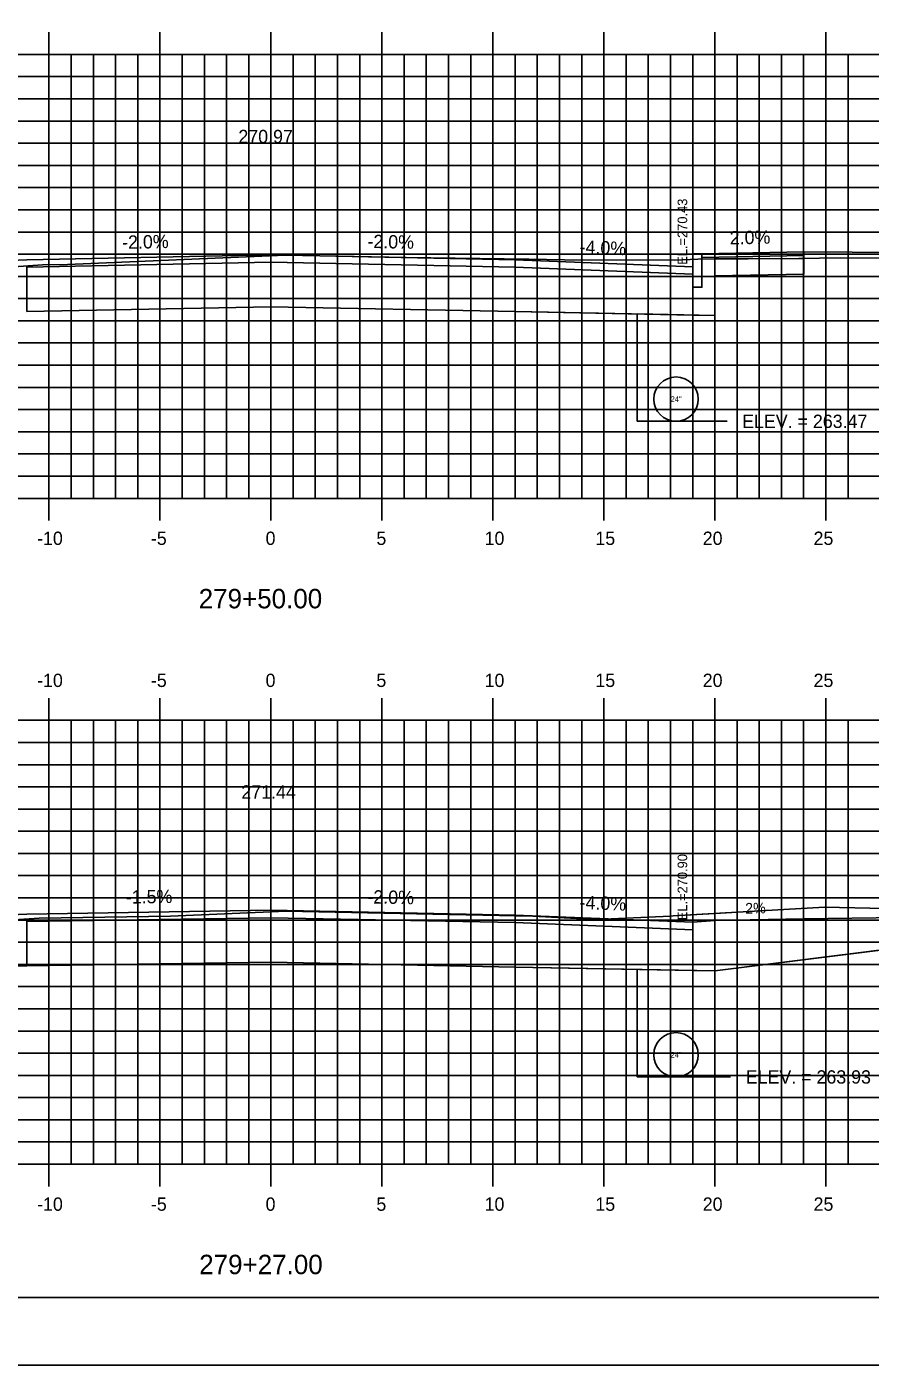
# Model space of a CAD drawing. Extents: x 854899 to 855069, y 366268 to 366378.
# Drawn here: x 854970.8 to 855008.8, y 366268.2 to 366328.5 of the extents above; entities that cross this region are included whole.
import ezdxf

# ---------------------------------------------------------------- set-up
doc = ezdxf.new("R2010")
doc.units = 0
for name, color, linetype in [('ANNOTATION', 7, 'Continuous'), ('BORDER', 7, 'Continuous'), ('D_Curb_Type_1_Rt', 7, 'Continuous'), ('D_Roadway_Centerline', 7, 'Continuous'), ('D_Roadway_Centerline_Text', 7, 'Continuous'), ('D_Roadway_Drive_Gravel_RT', 7, 'Continuous'), ('D_Roadway_Drive_SubGrade', 7, 'Continuous'), ('D_Roadway_Edge_Shoulder', 7, 'Continuous'), ('D_Roadway_FinishedGrade', 7, 'Continuous'), ('D_Roadway_Sidewalks_Paved', 7, 'Continuous'), ('D_Roadway_SubGrade', 7, 'Continuous'), ('D_Text_Standard', 7, 'Continuous'), ('H_V ANNOTATION', 7, 'Continuous'), ('JUNK COM EXC', 7, 'Continuous'), ('junk strct exc', 7, 'Continuous'), ('MAJOR', 7, 'Continuous'), ('MINOR', 7, 'Continuous'), ('PDRAIN', 7, 'Continuous'), ('PLOT BOUNDARY', 7, 'Continuous'), ('S_Roadway_Centerline', 7, 'Continuous')]:
    doc.layers.add(name, color=color, linetype=linetype)

msp = doc.modelspace()

# ---------------------------------------------------------------- linework, layer by layer
at = {"layer": 'BORDER'}
msp.add_line((854906.774, 366271.236), (855066.774, 366271.236), dxfattribs=at)
at = {"layer": 'D_Curb_Type_1_Rt'}
msp.add_lwpolyline([(855001.193, 366318.249), (855001.193, 366316.749), (855000.777, 366316.749), (855000.777, 366318.249)], close=True, dxfattribs=at)
at = {"layer": 'D_Roadway_Centerline'}
msp.add_lwpolyline([(854970.774, 366317.986), (854981.774, 366318.206), (854992.774, 366317.986)], dxfattribs=at)
at = {"layer": 'D_Roadway_Drive_Gravel_RT'}
for p, q in [((855001.774, 366288.213), (855005.774, 366288.293)), ((855005.774, 366288.293), (855032.774, 366288.63)), ((855000.774, 366288.133), (855001.774, 366288.213))]:
    msp.add_line(p, q, dxfattribs=at)
at = {"layer": 'D_Roadway_Drive_SubGrade'}
for p, q in [((855000.775, 366315.492), (855001.775, 366315.472)), ((855001.774, 366285.94), (855011.774, 366287.201)), ((855000.774, 366285.96), (855001.774, 366285.94))]:
    msp.add_line(p, q, dxfattribs=at)
at = {"layer": 'D_Roadway_Edge_Shoulder'}
msp.add_line((855000.774, 366317.665), (855000.774, 366317.333), dxfattribs=at)
for points in [[(854962.774, 366317.666), (854970.774, 366317.986), (854981.774, 366318.206), (854992.774, 366317.986), (855000.774, 366317.665)], [(854962.774, 366288.184), (854970.774, 366288.504), (854981.774, 366288.674), (854992.774, 366288.453), (855000.774, 366288.133)]]:
    msp.add_lwpolyline(points, dxfattribs=at)
at = {"layer": 'D_Roadway_FinishedGrade'}
msp.add_line((855005.782, 366318.34), (855023.706, 366318.244), dxfattribs=at)
at = {"layer": 'D_Roadway_Sidewalks_Paved'}
msp.add_lwpolyline([(855001.194, 366318.248), (855005.782, 366318.34), (855005.782, 366318.173), (855001.194, 366318.081)], close=True, dxfattribs=at)
at = {"layer": 'D_Roadway_SubGrade'}
for points in [[(854970.774, 366315.652), (854970.774, 366317.652), (854981.774, 366317.872), (854992.774, 366317.652), (854992.774, 366315.652), (854981.774, 366315.872)], [(854992.774, 366317.652), (855000.774, 366317.333), (855000.774, 366315.493), (854992.774, 366315.652)], [(854970.774, 366286.171), (854970.774, 366288.171), (854981.774, 366288.34), (854992.774, 366288.12), (854992.774, 366286.12), (854981.774, 366286.34)], [(854992.774, 366288.12), (855000.774, 366287.8), (855000.774, 366285.96), (854992.774, 366286.12)]]:
    msp.add_lwpolyline(points, close=True, dxfattribs=at)
msp.add_lwpolyline([(855005.782, 366318.173), (855005.782, 366317.34), (855001.777, 366317.26), (855001.777, 366315.472), (855000.777, 366315.492)], dxfattribs=at)
at = {"layer": 'D_Text_Standard'}
for points in [[(855001.775, 366310.706), (855001.642, 366310.706), (855002.322, 366310.706)], [(855001.774, 366281.166), (855001.804, 366281.166), (855002.484, 366281.166)]]:
    msp.add_lwpolyline(points, dxfattribs=at)
at = {"layer": 'JUNK COM EXC'}
for points in [[(854970.774, 366315.652), (854981.774, 366315.872), (854992.774, 366315.652), (855001.775, 366315.472), (855001.777, 366317.26), (855005.782, 366317.34), (855005.782, 366318.046), (855003.277, 366318.029), (855001.774, 366318.021), (855001.001, 366318.016), (854999.964, 366317.964), (854995.003, 366317.976), (854993.388, 366318.007), (854987.873, 366318.081), (854982.41, 366318.199), (854972.612, 366317.778), (854971.488, 366317.76), (854970.188, 366317.674)], [(855001.774, 366288.529), (854999.893, 366288.419), (854999.77, 366288.409), (854996.433, 366288.257), (854996.105, 366288.282), (854993.573, 366288.403), (854989.068, 366288.497), (854982.457, 366288.64), (854977.246, 366288.416), (854971.338, 366288.32), (854966.506, 366288), (854965.316, 366287.948), (854963.414, 366288.013), (854961.774, 366288.084), (854961.774, 366285.991), (854970.774, 366286.171), (854981.774, 366286.34), (854992.774, 366286.12), (855001.778, 366285.94), (855001.778, 366287.562)]]:
    msp.add_lwpolyline(points, dxfattribs=at)
msp.add_lwpolyline([(855001.774, 366285.94), (855011.774, 366287.201), (855032.774, 366287.463), (855032.774, 366288.63), (855029.947, 366288.626), (855028.392, 366288.676), (855026.837, 366288.727), (855022.702, 366288.715), (855018.567, 366288.702), (855014.002, 366288.726), (855009.438, 366288.75), (855008.079, 366288.784), (855006.72, 366288.819), (855003.306, 366288.619), (855001.774, 366288.529)], close=True, dxfattribs=at)
at = {"layer": 'junk strct exc'}
msp.add_lwpolyline([(854998.275, 366315.542), (854998.275, 366310.706), (855001.775, 366310.706), (855001.775, 366315.472)], close=True, dxfattribs=at)
at = {"layer": 'MAJOR'}
for p, q in [((854971.774, 366328.238), (854971.774, 366327.236)), ((854976.774, 366328.238), (854976.774, 366327.236)), ((854981.774, 366328.238), (854981.774, 366327.236)), ((854986.774, 366328.238), (854986.774, 366327.236)), ((854991.774, 366328.238), (854991.774, 366327.236)), ((854996.774, 366328.238), (854996.774, 366327.236)), ((855001.774, 366328.238), (855001.774, 366327.236)), ((855006.774, 366328.238), (855006.774, 366327.236)), ((854911.774, 366327.236), (855051.774, 366327.236)), ((854911.774, 366327.236), (855051.774, 366327.236)), ((854971.774, 366307.236), (854971.774, 366327.236)), ((854976.774, 366307.236), (854976.774, 366327.236)), ((854981.774, 366307.236), (854981.774, 366327.236)), ((854986.774, 366307.236), (854986.774, 366327.236)), ((854991.774, 366307.236), (854991.774, 366327.236)), ((854996.774, 366307.236), (854996.774, 366327.236)), ((855001.774, 366307.236), (855001.774, 366327.236)), ((855006.774, 366307.236), (855006.774, 366327.236)), ((854911.774, 366322.236), (855051.774, 366322.236)), ((854911.774, 366317.236), (855051.774, 366317.236)), ((854911.774, 366312.236), (855051.774, 366312.236)), ((854911.774, 366307.236), (855051.774, 366307.236)), ((854911.774, 366307.236), (855051.774, 366307.236)), ((854971.774, 366306.234), (854971.774, 366307.236)), ((854976.774, 366306.234), (854976.774, 366307.236)), ((854981.774, 366306.234), (854981.774, 366307.236)), ((854986.774, 366306.234), (854986.774, 366307.236)), ((854991.774, 366306.234), (854991.774, 366307.236)), ((854996.774, 366306.234), (854996.774, 366307.236)), ((855001.774, 366306.234), (855001.774, 366307.236)), ((855006.774, 366306.234), (855006.774, 366307.236)), ((854971.774, 366298.238), (854971.774, 366297.236)), ((854976.774, 366298.238), (854976.774, 366297.236)), ((854981.774, 366298.238), (854981.774, 366297.236)), ((854986.774, 366298.238), (854986.774, 366297.236)), ((854991.774, 366298.238), (854991.774, 366297.236)), ((854996.774, 366298.238), (854996.774, 366297.236)), ((855001.774, 366298.238), (855001.774, 366297.236)), ((855006.774, 366298.238), (855006.774, 366297.236)), ((854911.774, 366297.236), (855051.774, 366297.236)), ((854911.774, 366297.236), (855051.774, 366297.236)), ((854971.774, 366277.236), (854971.774, 366297.236)), ((854976.774, 366277.236), (854976.774, 366297.236)), ((854981.774, 366277.236), (854981.774, 366297.236)), ((854986.774, 366277.236), (854986.774, 366297.236)), ((854991.774, 366277.236), (854991.774, 366297.236)), ((854996.774, 366277.236), (854996.774, 366297.236)), ((855001.774, 366277.236), (855001.774, 366297.236)), ((855006.774, 366277.236), (855006.774, 366297.236)), ((854911.774, 366292.236), (855051.774, 366292.236)), ((854911.774, 366287.236), (855051.774, 366287.236)), ((854911.774, 366282.236), (855051.774, 366282.236)), ((854911.774, 366277.236), (855051.774, 366277.236)), ((854911.774, 366277.236), (855051.774, 366277.236)), ((854971.774, 366276.234), (854971.774, 366277.236)), ((854976.774, 366276.234), (854976.774, 366277.236)), ((854981.774, 366276.234), (854981.774, 366277.236)), ((854986.774, 366276.234), (854986.774, 366277.236)), ((854991.774, 366276.234), (854991.774, 366277.236)), ((854996.774, 366276.234), (854996.774, 366277.236)), ((855001.774, 366276.234), (855001.774, 366277.236)), ((855006.774, 366276.234), (855006.774, 366277.236))]:
    msp.add_line(p, q, dxfattribs=at)
at = {"layer": 'MINOR'}
for p, q in [((854972.774, 366307.236), (854972.774, 366327.236)), ((854973.774, 366307.236), (854973.774, 366327.236)), ((854974.774, 366307.236), (854974.774, 366327.236)), ((854975.774, 366307.236), (854975.774, 366327.236)), ((854977.774, 366307.236), (854977.774, 366327.236)), ((854978.774, 366307.236), (854978.774, 366327.236)), ((854979.774, 366307.236), (854979.774, 366327.236)), ((854980.774, 366307.236), (854980.774, 366327.236)), ((854982.774, 366307.236), (854982.774, 366327.236)), ((854983.774, 366307.236), (854983.774, 366327.236)), ((854984.774, 366307.236), (854984.774, 366327.236)), ((854985.774, 366307.236), (854985.774, 366327.236)), ((854987.774, 366307.236), (854987.774, 366327.236)), ((854988.774, 366307.236), (854988.774, 366327.236)), ((854989.774, 366307.236), (854989.774, 366327.236)), ((854990.774, 366307.236), (854990.774, 366327.236)), ((854992.774, 366307.236), (854992.774, 366327.236)), ((854993.774, 366307.236), (854993.774, 366327.236)), ((854994.774, 366307.236), (854994.774, 366327.236)), ((854995.774, 366307.236), (854995.774, 366327.236)), ((854997.774, 366307.236), (854997.774, 366327.236)), ((854998.774, 366307.236), (854998.774, 366327.236)), ((854999.774, 366307.236), (854999.774, 366327.236)), ((855000.774, 366307.236), (855000.774, 366327.236)), ((855002.774, 366307.236), (855002.774, 366327.236)), ((855003.774, 366307.236), (855003.774, 366327.236)), ((855004.774, 366307.236), (855004.774, 366327.236)), ((855005.774, 366307.236), (855005.774, 366327.236)), ((855007.774, 366307.236), (855007.774, 366327.236)), ((854911.774, 366326.236), (855051.774, 366326.236)), ((854911.774, 366325.236), (855051.774, 366325.236)), ((854911.774, 366324.236), (855051.774, 366324.236)), ((854911.774, 366323.236), (855051.774, 366323.236)), ((854911.774, 366321.236), (855051.774, 366321.236)), ((854911.774, 366320.236), (855051.774, 366320.236)), ((854911.774, 366319.236), (855051.774, 366319.236)), ((854911.774, 366318.236), (855051.774, 366318.236)), ((854911.774, 366316.236), (855051.774, 366316.236)), ((854911.774, 366315.236), (855051.774, 366315.236)), ((854911.774, 366314.236), (855051.774, 366314.236)), ((854911.774, 366313.236), (855051.774, 366313.236)), ((854911.774, 366311.236), (855051.774, 366311.236)), ((854911.774, 366310.236), (855051.774, 366310.236)), ((854911.774, 366309.236), (855051.774, 366309.236)), ((854911.774, 366308.236), (855051.774, 366308.236)), ((854972.774, 366277.236), (854972.774, 366297.236)), ((854973.774, 366277.236), (854973.774, 366297.236)), ((854974.774, 366277.236), (854974.774, 366297.236)), ((854975.774, 366277.236), (854975.774, 366297.236)), ((854977.774, 366277.236), (854977.774, 366297.236)), ((854978.774, 366277.236), (854978.774, 366297.236)), ((854979.774, 366277.236), (854979.774, 366297.236)), ((854980.774, 366277.236), (854980.774, 366297.236)), ((854982.774, 366277.236), (854982.774, 366297.236)), ((854983.774, 366277.236), (854983.774, 366297.236)), ((854984.774, 366277.236), (854984.774, 366297.236)), ((854985.774, 366277.236), (854985.774, 366297.236)), ((854987.774, 366277.236), (854987.774, 366297.236)), ((854988.774, 366277.236), (854988.774, 366297.236)), ((854989.774, 366277.236), (854989.774, 366297.236)), ((854990.774, 366277.236), (854990.774, 366297.236)), ((854992.774, 366277.236), (854992.774, 366297.236)), ((854993.774, 366277.236), (854993.774, 366297.236)), ((854994.774, 366277.236), (854994.774, 366297.236)), ((854995.774, 366277.236), (854995.774, 366297.236)), ((854997.774, 366277.236), (854997.774, 366297.236)), ((854998.774, 366277.236), (854998.774, 366297.236)), ((854999.774, 366277.236), (854999.774, 366297.236)), ((855000.774, 366277.236), (855000.774, 366297.236)), ((855002.774, 366277.236), (855002.774, 366297.236)), ((855003.774, 366277.236), (855003.774, 366297.236)), ((855004.774, 366277.236), (855004.774, 366297.236)), ((855005.774, 366277.236), (855005.774, 366297.236)), ((855007.774, 366277.236), (855007.774, 366297.236)), ((854911.774, 366296.236), (855051.774, 366296.236)), ((854911.774, 366295.236), (855051.774, 366295.236)), ((854911.774, 366294.236), (855051.774, 366294.236)), ((854911.774, 366293.236), (855051.774, 366293.236)), ((854911.774, 366291.236), (855051.774, 366291.236)), ((854911.774, 366290.236), (855051.774, 366290.236)), ((854911.774, 366289.236), (855051.774, 366289.236)), ((854911.774, 366288.236), (855051.774, 366288.236)), ((854911.774, 366286.236), (855051.774, 366286.236)), ((854911.774, 366285.236), (855051.774, 366285.236)), ((854911.774, 366284.236), (855051.774, 366284.236)), ((854911.774, 366283.236), (855051.774, 366283.236)), ((854911.774, 366281.236), (855051.774, 366281.236)), ((854911.774, 366280.236), (855051.774, 366280.236)), ((854911.774, 366279.236), (855051.774, 366279.236)), ((854911.774, 366278.236), (855051.774, 366278.236))]:
    msp.add_line(p, q, dxfattribs=at)
at = {"layer": 'PDRAIN'}
for points in [[(854998.275, 366315.542), (854998.275, 366310.706), (855001.775, 366310.706), (855001.775, 366315.472)], [(854998.274, 366286.002), (854998.274, 366281.166), (855001.774, 366281.166), (855001.774, 366285.932)]]:
    msp.add_lwpolyline(points, dxfattribs=at)
for centre in [(855000.025, 366311.706), (855000.024, 366282.166)]:
    msp.add_circle(centre, 1, dxfattribs=at)
at = {"layer": 'PLOT BOUNDARY'}
msp.add_lwpolyline([(854898.681, 366268.177), (855068.681, 366268.177), (855068.681, 366378.177), (854898.681, 366378.177)], close=True, dxfattribs=at)
at = {"layer": 'S_Roadway_Centerline'}
for points in [[(854924.068, 366316.94), (854929.097, 366317.144), (854935.552, 366317.258), (854949.789, 366317.41), (854960.814, 366317.707), (854961.589, 366317.66), (854964.403, 366317.388), (854965.385, 366317.346), (854970.188, 366317.674), (854971.488, 366317.76), (854972.612, 366317.778), (854982.41, 366318.199), (854987.873, 366318.081), (854993.388, 366318.007), (854995.003, 366317.976), (854999.964, 366317.964), (855001.001, 366318.016), (855005.553, 366318.042), (855007.414, 366318.074), (855018.059, 366317.982)], [(854920.631, 366286.642), (854924.888, 366286.755), (854939.58, 366287.166), (854945.963, 366287.37), (854957.486, 366287.942), (854961.059, 366288.051), (854961.286, 366288.106), (854963.414, 366288.013), (854965.316, 366287.948), (854966.506, 366288), (854971.338, 366288.32), (854977.246, 366288.416), (854982.457, 366288.64), (854989.068, 366288.497), (854993.573, 366288.403), (854996.105, 366288.282), (854996.433, 366288.257), (854999.77, 366288.409), (854999.893, 366288.419), (855006.72, 366288.819), (855009.438, 366288.75)]]:
    msp.add_lwpolyline(points, dxfattribs=at)

# ---------------------------------------------------------------- texts
at = {"layer": 'ANNOTATION'}
for s, rotation, p in [('-2.0%', 1.14576, (854975.077, 366318.472)), ('-2.0%', 358.85424, (854986.117, 366318.519)), ('2.0%', 1.14846, (855002.45, 366318.674)), ('-4.0%', 357.70944, (854995.67, 366318.27)), ('-1.5%', 0.88229, (854975.242, 366288.973)), ('-2.0%', 358.85424, (854986.117, 366288.987)), ('-4.0%', 357.70922, (854995.67, 366288.738))]:
    msp.add_text(s, height=0.6, rotation=rotation, dxfattribs=at).set_placement(p)
at = {"layer": 'D_Roadway_Centerline_Text'}
for s, p in [('270.97', (854980.308, 366323.238)), ('271.44', (854980.442, 366293.706))]:
    msp.add_text(s, height=0.6, dxfattribs=at).set_placement(p)
at = {"layer": 'D_Roadway_Drive_Gravel_RT'}
msp.add_text('2%', height=0.48, rotation=1.19222, dxfattribs=at).set_placement((855003.144, 366288.522))
at = {"layer": 'D_Text_Standard'}
for s, p in [(' EL.=270.43', (855000.529, 366317.597)), (' EL.=270.90', (855000.529, 366288.065))]:
    msp.add_text(s, height=0.4335, rotation=90, dxfattribs=at).set_placement(p)
for s, p in [('ELEV. = 263.47', (855003.002, 366310.406)), ('ELEV. = 263.93', (855003.164, 366280.866))]:
    msp.add_text(s, height=0.6, dxfattribs=at).set_placement(p)
at = {"layer": 'H_V ANNOTATION'}
for s, height, p in [('-10', 0.6, (854971.239, 366305.136)), ('-5', 0.6, (854976.365, 366305.136)), ('0', 0.6, (854981.533, 366305.136)), ('5', 0.6, (854986.525, 366305.136)), ('10', 0.6, (854991.399, 366305.136)), ('15', 0.6, (854996.391, 366305.136)), ('20', 0.6, (855001.228, 366305.136)), ('25', 0.6, (855006.22, 366305.136)), ('279+50.00', 0.875, (854978.52, 366302.28)), ('-10', 0.6, (854971.239, 366298.736)), ('-5', 0.6, (854976.365, 366298.736)), ('0', 0.6, (854981.533, 366298.736)), ('5', 0.6, (854986.525, 366298.736)), ('10', 0.6, (854991.399, 366298.736)), ('15', 0.6, (854996.391, 366298.736)), ('20', 0.6, (855001.228, 366298.736)), ('25', 0.6, (855006.22, 366298.736)), ('-10', 0.6, (854971.239, 366275.136)), ('-5', 0.6, (854976.365, 366275.136)), ('0', 0.6, (854981.533, 366275.136)), ('5', 0.6, (854986.525, 366275.136)), ('10', 0.6, (854991.399, 366275.136)), ('15', 0.6, (854996.391, 366275.136)), ('20', 0.6, (855001.228, 366275.136)), ('25', 0.6, (855006.22, 366275.136)), ('279+27.00', 0.875, (854978.543, 366272.28))]:
    msp.add_text(s, height=height, dxfattribs=at).set_placement(p)
at = {"layer": 'PDRAIN'}
for p in [(854999.783, 366311.581), (854999.782, 366282.041)]:
    msp.add_text('24"', height=0.25, dxfattribs=at).set_placement(p)
at = {"layer": 'S_Roadway_Centerline'}
for s, p in [('C', (854982.405, 366318.199)), ('L', (854982.41, 366318.192)), ('C', (854982.451, 366288.64)), ('L', (854982.457, 366288.633))]:
    msp.add_text(s, height=0.0146, dxfattribs=at).set_placement(p)

doc.saveas('drawing.dxf')
